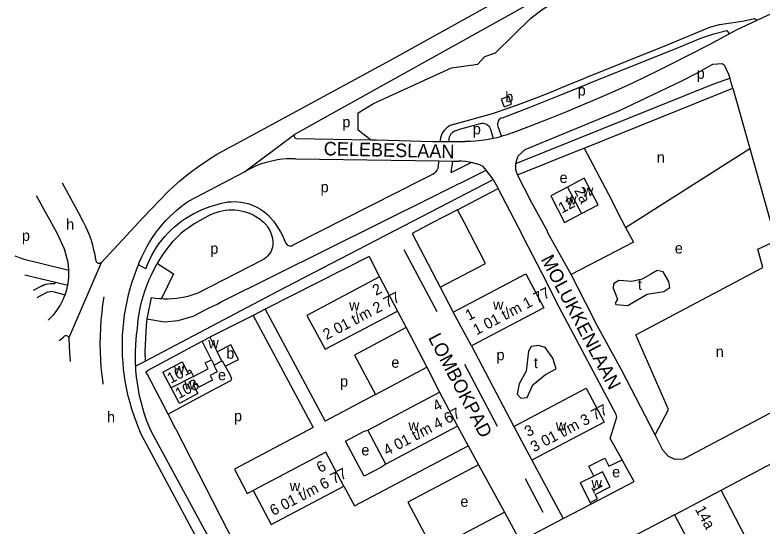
# Model space of a CAD drawing. Extents: x 162883 to 165538, y 383986 to 385172.
# Drawn here: x 162883.5 to 163159.5, y 384119.8 to 384308.7 of the extents above; entities that cross this region are included whole.
import ezdxf

# ---------------------------------------------------------------- set-up
doc = ezdxf.new("R2010")
doc.units = 0
for name, color, linetype in [('BLT_Basislijn', 7, 'Continuous'), ('BLT_Bebouwing', 7, 'Continuous'), ('BLT_Centroide', 7, 'Continuous'), ('BLT_Huisnummer', 7, 'Continuous'), ('BLT_Huisnummer_reeks', 7, 'Continuous'), ('BLT_Onderverdeling_panden', 7, 'Continuous'), ('BLT_Straatnaam', 7, 'Continuous'), ('BLT_Vlakafsluiter', 7, 'Continuous')]:
    doc.layers.add(name, color=color, linetype=linetype)

msp = doc.modelspace()

# ---------------------------------------------------------------- linework, layer by layer
at = {"layer": 'BLT_Basislijn'}
for p, q in [((162986.87, 384264.62), (163091.98, 384323.19)), ((163157.73, 384306.76), (163164.89, 384310.08)), ((163148.65, 384281.68), (163147.58, 384285.42)), ((163093.77, 384259.52), (163148.65, 384281.68)), ((163059.14, 384266.53), (163060.13, 384263.04)), ((163061.92, 384267.49), (163063.19, 384263.81)), ((163040.53, 384261.92), (163043.75, 384261.91)), ((163043.75, 384261.91), (163049.7, 384261.9)), ((162987.09, 384255.55), (163040.19, 384254.8)), ((163039.85, 384252.56), (163040.19, 384254.8)), ((163040.19, 384254.8), (163045.23, 384254.73)), ((163044.59, 384250.48), (163045.23, 384254.73)), ((163044.59, 384250.48), (163052.03, 384254.18)), ((163045.23, 384254.73), (163047.47, 384254.7)), ((163057.58, 384251.35), (163056.47, 384252.77)), ((162947.59, 384239.87), (162968.23, 384250.72)), ((162959.63, 384202.67), (163057.58, 384251.35)), ((163033.92, 384247.88), (163037.42, 384249.58)), ((163060.08, 384248.15), (163057.58, 384251.35)), ((162980.56, 384206.62), (163060.21, 384247.92)), ((162986.52, 384223.87), (163033.92, 384247.88)), ((163060.08, 384248.15), (163060.21, 384247.92)), ((163060.21, 384247.92), (163062.05, 384244.57)), ((162900.92, 384246.65), (162907.76, 384233.96)), ((163047.04, 384236.76), (163062.05, 384244.57)), ((163049.57, 384231.91), (163047.04, 384236.76)), ((163030.18, 384228), (163040.58, 384208.17)), ((163027.21, 384222.06), (163039.33, 384199.13)), ((163014.37, 384219.4), (162975.93, 384199.95)), ((163014.37, 384219.4), (163018.15, 384211.89)), ((162886.34, 384218.61), (162903.39, 384214.37)), ((162931.86, 384214.91), (162929.1, 384216.37)), ((162936.1, 384216.84), (162942.02, 384213.02)), ((162951.17, 384206.07), (162974.94, 384218.17)), ((162887.16, 384212.69), (162898.49, 384209.96)), ((162942.02, 384213.02), (162937.58, 384203.89)), ((163097.06, 384196.86), (163089, 384212.79)), ((162893.49, 384208.65), (162890.2, 384206.85)), ((162898.15, 384209.41), (162898.49, 384209.96)), ((162898.49, 384209.96), (162902.99, 384208.88)), ((163040.58, 384208.17), (163045.43, 384198.93)), ((162895.42, 384206.24), (162891.6, 384204.16)), ((162898, 384206.46), (162902, 384205.26)), ((162931.54, 384180.82), (162980.56, 384206.62)), ((162933.82, 384204.36), (162932.16, 384196.43)), ((162975.93, 384199.95), (162971.47, 384197.7)), ((162975.93, 384199.95), (162998.05, 384158.59)), ((162971.47, 384197.7), (162955.48, 384189.61)), ((162971.47, 384197.7), (162993.62, 384156.26)), ((163024.83, 384199.3), (163028, 384193.17)), ((163028, 384193.17), (163035.59, 384178.53)), ((163052.1, 384186.44), (163067.81, 384156.67)), ((162928.08, 384179), (162931.54, 384180.82)), ((163016.64, 384168.41), (163035.59, 384178.53)), ((163035.59, 384178.53), (163040.36, 384169.32)), ((163049.61, 384179.71), (163061.69, 384156.78)), ((162955.9, 384169.7), (162940.04, 384161.24)), ((163016.64, 384168.41), (162998.05, 384158.59)), ((162942.96, 384155.66), (162940.04, 384161.24)), ((162942.96, 384155.66), (162969.69, 384103.29)), ((163046.99, 384156.8), (163050.96, 384149.52)), ((162978.36, 384063.54), (162930.26, 384153.6)), ((163050.96, 384149.52), (163054.76, 384142.52)), ((163107.8, 384144.36), (163106.98, 384145.87)), ((163054.76, 384142.52), (163064.31, 384124.97)), ((163074.42, 384144.14), (163086.07, 384122.62)), ((163109.4, 384141.42), (163107.8, 384144.36)), ((163112.19, 384136.27), (163109.4, 384141.42)), ((163072.01, 384137.36), (163078.49, 384124.96)), ((163096.28, 384127.96), (163112.19, 384136.27)), ((163127.21, 384124.05), (163144.43, 384133.05)), ((163095.95, 384128.59), (163096.28, 384127.96)), ((163086.07, 384122.62), (163096.28, 384127.96)), ((163064.31, 384124.97), (163070.12, 384114.29)), ((163070.12, 384114.29), (163086.07, 384122.62)), ((163127.21, 384124.05), (163111.93, 384116)), ((163127.21, 384124.05), (163137.93, 384103.6))]:
    msp.add_line(p, q, dxfattribs=at)
for points in [[(163014.85, 384262.6), (163010.31, 384266.1), (163010.26, 384272.54), (163015.98, 384275.99), (163044.78, 384289.14), (163054.55, 384290.51), (163057.11, 384293.33), (163061.01, 384294.75), (163074.05, 384307.52), (163078.61, 384311.03), (163103.23, 384326.02), (163147.41, 384351.74), (163305.54, 384443.59), (163406.25, 384500.5)], [(162964.15, 384260.53), (163022.21, 384292), (163067.54, 384317.25), (163097.69, 384334.8)], [(163140.23, 384304.16), (163143.81, 384305.23), (163148.84, 384305.98), (163152.9, 384306.52), (163156.75, 384307.37), (163157.73, 384306.76)], [(163147.4, 384301.79), (163150.01, 384303.2), (163157.73, 384306.76)], [(163094.73, 384285.75), (163124.82, 384297.84), (163140.23, 384304.16)], [(163136.91, 384300.09), (163141.67, 384301.8), (163146.48, 384302.98), (163147.4, 384301.79)], [(163095.43, 384283.34), (163129.53, 384297.09), (163136.91, 384300.09)], [(163125.25, 384290.24), (163139.85, 384297.74), (163147.4, 384301.79)], [(163068.53, 384253.78), (163069.4, 384256.67), (163071.93, 384258.96), (163106.57, 384273.35), (163129.83, 384284.42), (163135.11, 384287.03), (163141.33, 384290.48), (163144.71, 384290.76), (163145.5, 384290.32), (163147.16, 384286.87), (163147.58, 384285.42)], [(163096.07, 384276.75), (163101.24, 384278.94), (163106.38, 384281.19), (163111.49, 384283.52), (163116.56, 384285.92), (163121.6, 384288.4), (163125.25, 384290.24)], [(163064.59, 384273.86), (163070.52, 384276.02), (163076.43, 384278.26), (163082.31, 384280.57), (163088.15, 384282.96), (163093.97, 384285.42), (163094.73, 384285.75)], [(163068.53, 384253.78), (163141.69, 384283.23), (163147.58, 384285.42)], [(163063.56, 384270.76), (163074.04, 384274.81), (163084.49, 384278.93), (163094.9, 384283.12), (163095.43, 384283.34)], [(163148.65, 384281.68), (163154.99, 384259.32)], [(163067.13, 384265.14), (163073.9, 384267.71), (163080.65, 384270.37), (163087.37, 384273.09), (163094.06, 384275.89), (163096.07, 384276.75)], [(163045.69, 384268.38), (163059.89, 384272.25), (163064.59, 384273.86)], [(163063.56, 384270.76), (163063.15, 384270.6), (163062.77, 384270.36), (163062.43, 384270.06), (163062.16, 384269.71), (163061.95, 384269.31), (163061.82, 384268.88), (163061.77, 384268.44), (163061.79, 384267.99), (163061.92, 384267.49)], [(163045.69, 384268.38), (163044.98, 384268.16), (163044.3, 384267.86), (163043.66, 384267.48), (163043.06, 384267.04), (163042.51, 384266.54), (163042.02, 384265.99), (163041.59, 384265.38), (163041.23, 384264.73), (163040.93, 384264.05), (163040.72, 384263.34), (163040.58, 384262.61), (163040.53, 384261.92)], [(163046.09, 384265.84), (163048.17, 384266.58), (163055.53, 384268.61)], [(163055.53, 384268.61), (163056, 384268.7), (163056.48, 384268.72), (163056.96, 384268.65), (163057.42, 384268.5), (163057.85, 384268.29), (163058.24, 384268), (163058.57, 384267.65), (163058.85, 384267.26), (163059.05, 384266.82), (163059.14, 384266.53)], [(162986.87, 384264.62), (162986.74, 384264.36), (162986.67, 384264.09), (162986.67, 384263.81), (162986.76, 384263.55), (162986.92, 384263.32), (162987.13, 384263.14), (162987.32, 384263.05)], [(163046.09, 384265.84), (163045.6, 384265.61), (163045.14, 384265.32), (163044.74, 384264.96), (163044.4, 384264.55), (163044.12, 384264.09), (163043.9, 384263.59), (163043.77, 384263.07), (163043.72, 384262.53), (163043.75, 384261.91)], [(163063.19, 384263.81), (163061.51, 384263.36), (163060.13, 384263.04)], [(163067.13, 384265.14), (163065.28, 384264.47), (163063.41, 384263.87), (163063.19, 384263.81)], [(162940.12, 384243.54), (162942.18, 384245.46), (162944.29, 384247.32), (162946.45, 384249.11), (162948.67, 384250.85), (162950.93, 384252.52), (162953.24, 384254.13), (162955.59, 384255.67), (162957.98, 384257.14), (162960.42, 384258.55), (162962.9, 384259.88), (162964.15, 384260.53)], [(162987.32, 384263.05), (163014.85, 384262.6)], [(163014.85, 384262.6), (163017.02, 384262.56), (163037.88, 384261.92), (163040.53, 384261.92)], [(163060.13, 384263.04), (163059.6, 384262.92), (163057.67, 384262.55), (163055.72, 384262.27), (163053.77, 384262.07), (163051.81, 384261.95), (163049.85, 384261.9), (163049.7, 384261.9)], [(163069.16, 384249.6), (163092.4, 384258.96), (163093.77, 384259.52)], [(163093.77, 384259.52), (163103.84, 384240.43), (163105.95, 384236.06)], [(163109.02, 384230.23), (163154.99, 384259.32)], [(163154.99, 384259.32), (163164.64, 384225.27)], [(162987.09, 384255.55), (162985.45, 384255.58), (162983.81, 384255.52), (162982.17, 384255.39), (162980.54, 384255.17), (162978.92, 384254.87), (162977.32, 384254.5), (162975.74, 384254.05), (162974.18, 384253.52), (162972.65, 384252.92), (162971.15, 384252.25), (162969.68, 384251.5), (162968.23, 384250.72)], [(163039.85, 384252.56), (163039.68, 384252), (163039.45, 384251.47), (163039.14, 384250.98), (163038.77, 384250.53), (163038.34, 384250.14), (163037.87, 384249.81), (163037.42, 384249.58)], [(163052.03, 384254.18), (163051.24, 384254.34), (163049.88, 384254.54), (163048.52, 384254.66), (163047.47, 384254.7)], [(163056.47, 384252.77), (163055.2, 384253.28), (163053.9, 384253.71), (163052.58, 384254.06), (163052.03, 384254.18)], [(163069.16, 384249.6), (163068.54, 384251.42), (163068.53, 384253.78)], [(163089, 384212.79), (163080.33, 384228.21), (163080.25, 384228.82), (163074.48, 384239.32), (163069.16, 384249.6)], [(163071.39, 384226.53), (163070.83, 384227.62), (163062.05, 384244.57)], [(162891.36, 384242.05), (162898.99, 384228.21), (162901.73, 384222.09)], [(162915.4, 384217.28), (162930.9, 384233.91), (162940.12, 384243.54)], [(162930.46, 384219.53), (162931.3, 384221.31), (162932.22, 384223.05), (162933.21, 384224.76), (162934.26, 384226.42), (162935.38, 384228.05), (162936.57, 384229.62), (162937.82, 384231.14), (162939.13, 384232.62), (162940.49, 384234.03), (162941.92, 384235.4), (162943.4, 384236.7), (162944.93, 384237.94), (162946.51, 384239.12), (162947.59, 384239.87)], [(162931.86, 384214.91), (162932.48, 384216.52), (162933.18, 384218.11), (162933.94, 384219.66), (162934.78, 384221.17), (162935.68, 384222.65), (162936.66, 384224.08), (162937.7, 384225.46), (162938.8, 384226.79), (162939.96, 384228.07), (162941.18, 384229.3), (162942.46, 384230.47), (162943.78, 384231.58), (162945.16, 384232.62), (162946.59, 384233.61), (162948.06, 384234.52), (162949.57, 384235.36), (162951.11, 384236.14), (162952.69, 384236.84), (162954.3, 384237.47), (162955.94, 384238.02), (162957.38, 384238.44)], [(162957.38, 384238.44), (162958.54, 384238.85), (162959.73, 384239.18), (162960.93, 384239.44), (162962.15, 384239.61), (162963.38, 384239.71), (162964.61, 384239.73), (162965.84, 384239.66), (162967.06, 384239.52), (162968.27, 384239.3), (162969.47, 384238.99), (162970.64, 384238.62), (162971.78, 384238.17), (162972.9, 384237.64), (162973.97, 384237.04), (162975.01, 384236.38), (162976, 384235.65), (162976.87, 384234.91)], [(162955.62, 384234.81), (162956.68, 384235.32), (162957.78, 384235.74), (162958.9, 384236.1), (162960.04, 384236.38), (162961.2, 384236.58), (162962.37, 384236.7), (162963.55, 384236.74), (162964.72, 384236.7), (162965.89, 384236.58), (162967.05, 384236.38), (162968.19, 384236.1), (162969.32, 384235.75), (162970.41, 384235.32), (162971.47, 384234.82), (162972.5, 384234.24), (162973.49, 384233.6), (162973.66, 384233.48)], [(163047.04, 384236.76), (163037.39, 384231.74), (163030.18, 384228)], [(163105.95, 384236.06), (163109.02, 384230.23)], [(162913.36, 384218.27), (162913.06, 384220.07), (162912.68, 384221.86), (162912.23, 384223.63), (162911.7, 384225.38), (162911.09, 384227.11), (162910.4, 384228.8), (162909.65, 384230.47), (162908.82, 384232.1), (162907.92, 384233.69), (162907.76, 384233.96)], [(162955.62, 384234.81), (162953.61, 384233.77), (162951.63, 384232.66), (162949.7, 384231.48), (162947.81, 384230.23), (162945.96, 384228.92), (162944.59, 384227.88)], [(162973.66, 384233.48), (162974.44, 384232.92), (162975.17, 384232.3), (162975.85, 384231.61), (162976.48, 384230.88), (162977.03, 384230.09), (162977.52, 384229.26), (162977.94, 384228.4), (162978.29, 384227.5), (162978.56, 384226.57), (162978.69, 384225.99)], [(162976.87, 384234.91), (162977.93, 384233.74), (162978.94, 384232.53), (162979.87, 384231.26), (162980.75, 384229.95), (162981.55, 384228.6), (162982.29, 384227.21), (162982.95, 384225.78), (162983.45, 384224.56)], [(163040.58, 384208.17), (163057.38, 384216.93), (163049.57, 384231.91)], [(163109.02, 384230.23), (163111.99, 384224.71), (163089, 384212.79)], [(162936.1, 384216.84), (162937.02, 384218.37), (162938.17, 384220.12), (162939.38, 384221.82), (162940.65, 384223.48), (162941.99, 384225.08), (162943.39, 384226.64), (162944.59, 384227.88)], [(162978.69, 384225.99), (162978.79, 384225.23), (162978.81, 384224.46), (162978.75, 384223.69), (162978.61, 384222.94), (162978.4, 384222.2), (162978.1, 384221.49), (162977.74, 384220.82), (162977.31, 384220.19), (162976.81, 384219.6), (162976.26, 384219.07), (162975.65, 384218.6), (162974.94, 384218.17)], [(163106.98, 384145.87), (163103.44, 384152.16), (163105.81, 384160.1), (163105.64, 384161.07), (163084.5, 384200.77), (163078.18, 384213.47), (163071.39, 384226.53)], [(163119.97, 384153.58), (163124.89, 384162.96), (163112.87, 384190.51), (163159.83, 384215.45), (163157.97, 384222.16), (163164.64, 384225.27)], [(163164.64, 384225.27), (163172.33, 384198.16), (163175.01, 384186.95), (163175.17, 384179.87), (163174.12, 384175.33), (163172.03, 384170.67), (163170.74, 384168.73), (163167.86, 384165.38), (163164.34, 384162.52), (163131.08, 384144.97), (163130.29, 384144.62), (163127.42, 384144.46), (163124.88, 384145.57), (163122.87, 384147.94), (163119.97, 384153.58)], [(162903.39, 384214.37), (162903.38, 384214.57), (162903.27, 384215.94), (162903.08, 384217.3), (162902.81, 384218.65), (162902.46, 384219.98), (162902.03, 384221.29), (162901.73, 384222.09)], [(162983.45, 384224.56), (162983.64, 384224.21), (162983.9, 384223.91), (162984.21, 384223.67), (162984.57, 384223.5), (162984.95, 384223.41), (162985.34, 384223.39), (162985.73, 384223.45), (162986.1, 384223.59), (162986.43, 384223.8), (162986.52, 384223.87)], [(162883.48, 384219.76), (162883.84, 384219.57), (162884.99, 384219.08), (162886.18, 384218.66), (162886.34, 384218.61)], [(162929.1, 384216.37), (162929.43, 384217.19), (162930.46, 384219.53)], [(162913.36, 384218.27), (162913.38, 384217.96), (162913.47, 384217.66), (162913.64, 384217.4), (162913.86, 384217.18), (162914.14, 384217.04), (162914.44, 384216.96), (162914.75, 384216.97), (162915.05, 384217.05), (162915.32, 384217.21), (162915.4, 384217.28)], [(162930.26, 384153.6), (162929.26, 384155.9), (162928.33, 384158.24), (162927.47, 384160.61), (162926.69, 384163), (162925.99, 384165.42), (162925.36, 384167.86), (162924.81, 384170.31), (162924.34, 384172.79), (162923.95, 384175.27), (162923.64, 384177.77), (162923.41, 384180.28), (162923.25, 384182.79), (162923.18, 384185.3), (162923.19, 384187.82), (162923.27, 384190.34), (162923.44, 384192.85), (162923.69, 384195.35), (162924.01, 384197.85), (162924.42, 384200.33), (162924.9, 384202.8), (162925.46, 384205.26), (162926.1, 384207.69), (162926.82, 384210.1), (162927.61, 384212.49), (162928.48, 384214.85), (162929.1, 384216.37)], [(162928.75, 384192.76), (162928.92, 384194.85), (162929.17, 384196.92), (162929.51, 384198.99), (162929.92, 384201.04), (162930.4, 384203.07), (162930.97, 384205.08), (162931.61, 384207.07), (162932.33, 384209.04), (162933.12, 384210.97), (162933.99, 384212.88), (162934.93, 384214.74), (162935.94, 384216.58), (162936.1, 384216.84)], [(162902.99, 384208.88), (162903.04, 384209.09), (162903.24, 384210.45), (162903.37, 384211.82), (162903.42, 384213.19), (162903.39, 384214.37)], [(162893.49, 384208.65), (162894.2, 384208.97), (162894.93, 384209.22), (162895.69, 384209.4), (162896.46, 384209.49), (162897.24, 384209.5), (162898.01, 384209.43), (162898.15, 384209.41)], [(162902, 384205.26), (162902.39, 384206.41), (162902.75, 384207.74), (162902.99, 384208.88)], [(162895.42, 384206.24), (162895.91, 384206.43), (162896.43, 384206.56), (162896.96, 384206.61), (162897.49, 384206.57), (162898, 384206.46)], [(162895.87, 384195.97), (162895.92, 384196.02), (162896.9, 384196.99), (162897.82, 384198.01), (162898.67, 384199.09), (162899.47, 384200.21), (162900.19, 384201.38), (162900.85, 384202.59), (162901.44, 384203.83), (162901.95, 384205.11), (162902, 384205.26)], [(162937.58, 384203.89), (162938.5, 384203.83), (162940.07, 384203.81), (162941.64, 384203.88), (162943.2, 384204.02), (162944.75, 384204.25), (162946.29, 384204.55), (162947.82, 384204.93), (162949.32, 384205.39), (162950.79, 384205.92), (162951.17, 384206.07)], [(162916.32, 384204.61), (162915.88, 384201.73), (162915.53, 384198.85), (162915.25, 384195.95), (162915.05, 384193.05), (162914.94, 384190.15), (162914.9, 384187.24), (162914.95, 384184.34), (162915.07, 384181.43), (162915.27, 384178.53), (162915.56, 384175.64), (162915.92, 384172.76), (162915.99, 384172.22)], [(162932.16, 384196.43), (162938.78, 384195.32), (162943.84, 384195.8), (162949.27, 384197.38), (162955.26, 384200.45), (162956.88, 384201.19), (162958.47, 384202.01), (162959.63, 384202.67)], [(162933.82, 384204.36), (162935.37, 384204.1), (162936.93, 384203.93), (162937.58, 384203.89)], [(162932.16, 384196.43), (162931.9, 384193.95), (162931.42, 384184.34), (162931.54, 384180.82)], [(163119.97, 384153.58), (163107.62, 384177.62), (163097.86, 384195.37), (163097.06, 384196.86)], [(162928.08, 384179), (162928.04, 384179.62), (162927.99, 384181.96), (162928.01, 384184.31), (162928.11, 384186.65), (162928.29, 384188.99), (162928.55, 384191.32), (162928.75, 384192.76)], [(163028, 384193.17), (163008.96, 384182.96), (163016.64, 384168.41)], [(162899.83, 384188.38), (162900.2, 384188.67), (162901.51, 384189.75)], [(162901.51, 384189.75), (162901.69, 384189.97), (162901.93, 384190.14), (162902.2, 384190.23), (162902.49, 384190.25), (162902.77, 384190.19), (162903.02, 384190.05), (162903.23, 384189.85), (162903.37, 384189.6), (162903.44, 384189.32)], [(162903.44, 384189.32), (162903.48, 384186.57), (162903.61, 384183.82), (162903.82, 384181.07), (162903.87, 384180.62)], [(162940.04, 384161.24), (162932.39, 384175.84), (162931.88, 384176.86), (162932.75, 384177.47), (162952.59, 384188.13)], [(162933.9, 384154.67), (162932.98, 384156.82), (162932.14, 384159.01), (162931.37, 384161.23), (162930.68, 384163.47), (162930.07, 384165.73), (162929.54, 384168.01), (162929.08, 384170.31), (162928.7, 384172.62), (162928.4, 384174.95), (162928.18, 384177.28), (162928.08, 384179)], [(162961.11, 384178.92), (162962.96, 384175.56), (162963.44, 384174.19), (162963.12, 384173.55), (162955.9, 384169.7)], [(163144.43, 384133.05), (163173.67, 384148.67), (163177.34, 384151.33), (163180.1, 384153.67), (163184.4, 384158.54), (163186.9, 384162.45), (163189.24, 384166.82)], [(162993.62, 384156.26), (162964.55, 384140.92), (162969.29, 384131.86), (162971.5, 384133.01)], [(162990.47, 384049.56), (162954.42, 384117.02), (162933.9, 384154.67)], [(163020.54, 384142.77), (163018.66, 384141.51), (163012.44, 384138.22), (163005.55, 384151.24), (163012.47, 384154.89), (163013.9, 384155.3)], [(163004.99, 384134.53), (163008.95, 384127.35), (163050.96, 384149.52)], [(163097.36, 384138.28), (163095.55, 384142), (163101.46, 384144.94), (163102.92, 384141.92), (163107.8, 384144.36)], [(163054.76, 384142.52), (163028.58, 384128.68), (163037.94, 384111.04), (163064.31, 384124.97)], [(163137.93, 384103.6), (163155.03, 384112.62), (163144.43, 384133.05)]]:
    msp.add_lwpolyline(points, dxfattribs=at)
for points in [[(163120.7, 384214.27), (163118.39, 384212.94), (163115.21, 384211.12), (163111.41, 384210.19), (163108.3, 384210.42), (163106.6, 384210.54), (163104.59, 384209.36), (163104.48, 384207.73), (163106.03, 384203.73), (163105.17, 384202.16), (163105.52, 384201.7), (163109.89, 384201.34), (163111.71, 384202.43), (163117.02, 384205.6), (163123.16, 384206.58), (163125.08, 384207.8), (163125.4, 384208.06), (163125.03, 384210.24), (163123.02, 384213.76)], [(163074.14, 384186.16), (163073.2, 384184.43), (163072.34, 384177.07), (163069.79, 384172.39), (163069.04, 384168.57), (163070.36, 384167.1), (163072.76, 384167.33), (163074.85, 384172), (163079.46, 384175.84), (163083.39, 384177.94), (163082.18, 384181.88), (163079.34, 384185.78), (163076.89, 384186.58)]]:
    msp.add_lwpolyline(points, close=True, dxfattribs=at)
at = {"layer": 'BLT_Bebouwing'}
for p, q in [((163018.15, 384211.89), (163024.83, 384199.3)), ((163052.1, 384186.44), (163045.43, 384198.93)), ((162952.59, 384188.13), (162955.48, 384189.61)), ((162955.48, 384189.61), (162958.21, 384184.27)), ((162957.08, 384179.36), (162959.94, 384180.9)), ((163013.9, 384155.3), (163040.36, 384169.32)), ((163040.36, 384169.32), (163046.99, 384156.8)), ((163046.99, 384156.8), (163020.54, 384142.77)), ((163067.81, 384156.67), (163074.42, 384144.14)), ((163020.54, 384142.77), (163013.9, 384155.3))]:
    msp.add_line(p, q, dxfattribs=at)
msp.add_lwpolyline([(163063.12, 384277.56), (163064.18, 384274.75), (163066.97, 384275.79), (163065.91, 384278.56)], close=True, dxfattribs=at)
for points in [[(163092.76, 384235.29), (163098.96, 384238.54), (163093.81, 384248.37), (163087.61, 384245.11)], [(163087.61, 384245.11), (163081.4, 384241.86), (163086.56, 384232.04), (163092.76, 384235.29)], [(163018.15, 384211.89), (162991.31, 384197.7), (162998.07, 384185.2), (163024.83, 384199.3)], [(163045.43, 384198.93), (163072.22, 384213.02), (163078.84, 384200.5), (163052.1, 384186.44)], [(162956.08, 384181.33), (162952.59, 384188.13)], [(162961.11, 384178.92), (162966.06, 384181.45), (162963.28, 384186.86), (162958.21, 384184.27)], [(162941.17, 384170.89), (162938.06, 384176.68), (162945.2, 384180.5)], [(162945.2, 384180.5), (162947.09, 384176.98), (162948.23, 384177.6), (162949.48, 384175.16)], [(162949.48, 384175.16), (162954.85, 384177.91), (162953.72, 384180.12), (162956.08, 384181.33)], [(162959.94, 384180.9), (162960.06, 384180.96), (162961.11, 384178.92)], [(162957.08, 384179.36), (162956.93, 384179.28), (162958.22, 384176.87), (162955.58, 384175.45), (162956.46, 384173.81), (162951.44, 384171.11), (162950.69, 384172.5), (162949.47, 384171.85), (162951.08, 384168.85), (162944.24, 384165.17), (162941.17, 384170.89)], [(163067.81, 384156.67), (163094.57, 384170.8), (163101.2, 384158.28), (163074.42, 384144.14)], [(163004.99, 384134.53), (162998.31, 384147.18), (162971.5, 384133.01)], [(163095.95, 384128.59), (163098.7, 384129.93), (163097.9, 384131.56), (163103.38, 384134.29), (163100.61, 384139.89), (163097.36, 384138.28)], [(163097.36, 384138.28), (163092.3, 384135.79), (163095.95, 384128.59)], [(162971.5, 384133.01), (162978.2, 384120.37), (163004.99, 384134.53)]]:
    msp.add_lwpolyline(points, dxfattribs=at)
at = {"layer": 'BLT_Onderverdeling_panden'}
for p, q in [((163087.61, 384245.11), (163092.76, 384235.29)), ((162959.94, 384180.9), (162958.21, 384184.27)), ((162956.08, 384181.33), (162957.08, 384179.36)), ((162956.08, 384181.33), (162957.08, 384179.36)), ((162949.48, 384175.16), (162941.17, 384170.89))]:
    msp.add_line(p, q, dxfattribs=at)
at = {"layer": 'BLT_Vlakafsluiter'}
for p, q in [((162968.23, 384250.72), (162986.87, 384264.62)), ((162903.44, 384189.32), (162915.4, 384217.28))]:
    msp.add_line(p, q, dxfattribs=at)

# ---------------------------------------------------------------- texts
at = {"layer": 'BLT_Centroide'}
for s, p in [('p', (163135.36, 384285.13)), ('b', (163064.62, 384276.45)), ('p', (163091.39, 384278.93)), ('p', (163004.43, 384267.19)), ('p', (163052.63, 384264.6)), ('n', (163120.61, 384254.13)), ('e', (163084.67, 384246.62)), ('p', (162996.39, 384243.17)), ('w', (163093.28, 384241.83)), ('w', (163087.08, 384238.58)), ('h', (162902.38, 384229.35)), ('p', (162886.05, 384225.22)), ('p', (162955.65, 384220.46)), ('e', (163127.27, 384220.55)), ('t', (163113.63, 384207.11)), ('w', (163006.93, 384199.5)), ('w', (163060.11, 384199.75)), ('w', (162954.91, 384185.48)), ('b', (162961.56, 384181.68)), ('p', (163061.39, 384181.12)), ('n', (163142.39, 384182.34)), ('e', (163022.53, 384178.35)), ('t', (163075.2, 384178.21)), ('w', (162942.23, 384175.97)), ('e', (162958.5, 384173.69)), ('w', (162946.09, 384170.31)), ('p', (163003.58, 384171.36)), ('h', (162917.5, 384158.12)), ('p', (162964.4, 384158.56)), ('w', (163028.86, 384155.1)), ('w', (163083.3, 384155.1)), ('e', (163011.45, 384145.95)), ('e', (163104.12, 384137.87)), ('w', (163096.46, 384133.8)), ('w', (162985, 384132.74)), ('e', (163048.05, 384126.96))]:
    msp.add_text(s, height=4, dxfattribs=at).set_placement(p)
at = {"layer": 'BLT_Huisnummer'}
for s, rotation, p in [('2a', 297.6806, (163089.97, 384243.9)), ('12', 27.6772, (163085.53, 384235.28)), ('101', 28.2458, (162941.05, 384172.36)), ('103', 28.2512, (162944.04, 384166.74)), ('1', 297.3021, (163096.23, 384134.25)), ('14a', 298.3021, (163134.63, 384126.08))]:
    msp.add_text(s, height=4, rotation=rotation, dxfattribs=at).set_placement(p)
at = {"layer": 'BLT_Huisnummer_reeks'}
for s, p in [('2', (163016.82, 384204.89)), ('1 01 t/m 1 77', (163053.99, 384190.3)), ('2 01 t/m 2 77', (162998.56, 384188.57)), ('1', (163051.17, 384195.63)), ('4', (163039.13, 384162.07)), ('3 01 t/m 3 77', (163075.24, 384147.04)), ('4 01 t/m 4 67', (163020.88, 384145.75)), ('3', (163073.02, 384152.68)), ('6', (162996.19, 384139.39)), ('6 01 t/m 6 77', (162978.95, 384123.51))]:
    msp.add_text(s, height=4, rotation=27.6751, dxfattribs=at).set_placement(p)
at = {"layer": 'BLT_Straatnaam'}
for s, height, rotation, p in [('CELEBESLAAN', 4.9999, 358.6406, (162997.51, 384256.87)), ('MOLUKKENLAAN', 5, 297.706, (163077.62, 384218.43)), ('LOMBOKPAD', 5, 297.706, (163035.98, 384189.46))]:
    msp.add_text(s, height=height, rotation=rotation, dxfattribs=at).set_placement(p)

doc.saveas('drawing.dxf')
